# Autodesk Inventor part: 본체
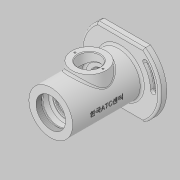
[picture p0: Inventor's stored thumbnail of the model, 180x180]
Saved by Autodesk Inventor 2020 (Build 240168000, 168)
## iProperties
Created: 2022-05
Part Number: 본체
Material: 일반
Document SubType Name: Modeling
Designer: User
Density: 1 g/cm^3
Appearance: 기본값
Mass: 255.264 g
Surface Area: 620.849 cm^2
Volume: 255.264 cm^3
Author: User
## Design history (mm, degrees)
sketch "스케치1"
  geometry: L1 (0, 0)-(115, 0); L2 (115, 0)-(115, 32); L3 (115, 32)-(0, 32); L4 (0, 32)-(0, 0); L5 (0, 22.5)-(8, 22.5); L6 (8, 22.5)-(8, 24); L7 (8, 24)-(11, 24); L8 (11, 24)-(11, 22.5); L9 (11, 22.5)-(22, 22.5); L10 (22, 22.5)-(22, 17.5); L11 (22, 17.5)-(24.25, 17.5); L12 (24.25, 17.5)-(24.25, 18.5); L13 (24.25, 18.5)-(26, 18.5); L14 (26, 18.5)-(26, 17.5); L15 (26, 17.5)-(37, 17.5); L16 (37, 17.5)-(37, 27); L17 (37, 27)-(75, 27); L18 (75, 27)-(75, 17.5); L19 (75, 17.5)-(86, 17.5); L20 (86, 17.5)-(86, 15); L21 (86, 15)-(91, 15); L22 (91, 15)-(91, 11); L23 (91, 11)-(93.7, 11); L24 (93.7, 11)-(93.7, 15); L25 (93.7, 15)-(101, 15); L26 (115, 32)-(115, 36); L27 (115, 36)-(112, 36); L28 (112, 36)-(112, 32); L29 (101, 15)-(101, 20); L30 (101, 20)-(115, 30); L31 (8, 24)-(8, 32); L32 (8, 22.5)-(8, 0)
  constraints: 64 end point, 24 perpendicular, 8 point on line, 3 vertical, 2 horizontal
  dimensions: "d0" = 3 distance of L26.end L27.end; "d1" = 112 distance between parallel lines of L28 L4; "d2" = 64 diameter of L3 L1; "d3" = 45 diameter of L9 L1; "d4" = 54 diameter of L17 L1; "d5" = 22 diameter of L23 L1; "d6" = 30 diameter of L25 L1; "d7" = 40 diameter of L29.end L1; "d8" = 60 diameter of L30.end L1; "d9" = 72 diameter of L27 L1; "d10" = 35 diameter of L15 L1; "d11" = 35 diameter of L11 L1; "d12" = 48 diameter of L7 L1; "d13" = 37 diameter of L13 L1; "d14" = 14 horizontal distance of L30.end L29.end; "d15" = 7.3 distance of L24.end L25.end; "d16" = 5 distance of L20.end L21.end; "d17" = 29 horizontal distance of L30.end L20.end; "d18" = 11 distance of L18.end L19.end; "d19" = 11 distance of L14.end L15.end; "d20" = 38 distance of L16.end L17.end; "d21" = 1.75 distance of L12.end L13.end; "d22" = 4 horizontal distance of L13.end L10.end; "d23" = 8 distance of L5.start L5.end; "d24" = 3 distance of L6.end L7.end; "d25" = 30 diameter of L21 L1; "d26" = 35 diameter of L19 L1
revolve "회전1" stored, may be unused: angle "d27" = 90 deg
sketch "스케치2"
  geometry: C1 r 32 at (0, 0) reference; 2 further points
  constraints: 1 coincident
hole "구멍1" sketch "스케치2" at (0, 0) diameter "d28" = 43.376; stored, may be unused: countersink angle "d32" = 90 deg, drill point angle "d34" = 0 deg; dims "d29" = 8, "d30" = 4, "d31" = 2, "d33" = 9
node "작업 평면1"
sketch "스케치3"
  geometry: L1 (-47, -33.985)-(-47, 33.985); L2 (47, 33.985)-(47, -33.985); L3 (0, 0)-(0, 48); L4 (0, 0)-(-30.854, 36.77); L5 (0, 0)-(0, -48); L6 (0, 0)-(30.854, -36.77); A1 r 48 centre (0, 0) between (0, 48) and (-30.854, 36.77); A2 r 4 centre (-30.854, 36.77) between (-33.425, 39.834) and (-28.283, 33.706); A3 r 58 centre (0, 0) between (47, 33.985) and (-47, 33.985); A4 r 58 centre (0, 0) between (-47, -33.985) and (47, -33.985); A5 r 4 centre (0, 48) between (0, 52) and (0, 44); A6 r 4 centre (0, -48) between (0, -52) and (0, -44); A7 r 4 centre (30.854, -36.77) between (28.283, -33.706) and (33.425, -39.834); A8 r 52 centre (0, 0) between (0, -52) and (33.425, -39.834); A9 r 52 centre (0, 0) between (0, 52) and (-33.425, 39.834); A10 r 44 centre (0, 0) between (0, 44) and (-28.283, 33.706); A11 r 44 centre (0, 0) between (0, -44) and (28.283, -33.706); A12 r 48 centre (0, 0) between (0, -48) and (30.854, -36.77); A13 r 50.25 centre (0, 0) between (0, -50.25) and (32.3, -38.494); A14 r 45.75 centre (0, 0) between (0, -45.75) and (29.408, -35.047); A15 r 2.25 centre (0, -48) between (0, -45.75) and (0, -50.25); A16 r 2.25 centre (30.854, -36.77) between (32.3, -38.494) and (29.408, -35.047); A17 r 48 centre (0, 0) between (0, 48) and (-30.854, 36.77); A18 r 50.25 centre (0, 0) between (0, 50.25) and (-32.3, 38.494); A19 r 45.75 centre (0, 0) between (0, 45.75) and (-29.408, 35.047); A20 r 2.25 centre (0, 48) between (0, 45.75) and (0, 50.25); A21 r 2.25 centre (-30.854, 36.77) between (-32.3, 38.494) and (-29.408, 35.047); 3 further points
  constraints: 44 point on circle, 21 centre point, 12 end point, 12 tangent, 10 coincident, 3 vertical, 2 midpoint, 1 parallel, 1 vertical alignment
  dimensions: "d37" = 96 diameter of A1; "d38" = 40 deg angle of L3 L4; "d39" = 8 diameter of A2; "d40" = 58 radius of A3; "d41" = 58 radius of A4; "d42" = 94 distance between parallel lines of L2 L1; "d44" = 8 diameter of A5; "d47" = 40 deg angle of L6 L5; "d48" = 8 diameter of A6; "d49" = 8 diameter of A7; "d51" = 47 distance between parallel lines of L3 L1 (= 0.5 x d42); "d62" = 4.5 radial gap between concentric circles of A13 A14; "d65" = 4.5 radial gap between concentric circles of A19 A18
extrude "돌출1" join sketch "스케치3" distance "d52" = 10; taper "d53" = 0 deg
revolve "회전2" stored, may be unused: angle "d54" = 90 deg
extrude "돌출3" cut sketch "스케치3" distance "d58" = 4.4; taper "d59" = 0 deg
extrude "돌출4" cut sketch "스케치3" extent not by distance; stored distance "d60" = 0; taper "d61" = 0 deg
extrude "돌출5" cut sketch "스케치3" extent not by distance; stored distance "d63" = 0; taper "d64" = 0 deg
node "작업 평면2"
sketch "스케치4"
  geometry: C1 r 25 at (56, 0); 1 further point
  constraints: 1 centre point, 1 horizontal alignment
  dimensions: "d67" = 50 diameter of C1; "d68" = 56 distance of C1.centre point (0, 0)
extrude "돌출6" join sketch "스케치4" stored distance "d69" = 10; taper "d70" = 5 deg
sketch "스케치5"
  geometry: C1 r 25 at (0, 0) reference; 2 further points
  constraints: 1 coincident
hole "구멍2" sketch "스케치5" at (0, 0) diameter "d71" = 32; stored, may be unused: countersink angle "d75" = 90 deg, drill point angle "d77" = 0 deg; dims "d72" = 90, "d73" = 4, "d74" = 2, "d76" = 38
fillet "모깎기1" dims "d78" = 3
fillet "모깎기2" dims "d79" = 3
fillet "모깎기3" dims "d80" = 0.6
fillet "모깎기4" dims "d81" = 0.5
chamfer "모따기1" distance "d82" = 0.7; stored, may be unused: second distance "d83" = 2, angle "d84" = 30 deg
fillet "모깎기5" dims "d85" = 3
fillet "모깎기6" dims "d86" = 3
fillet "모깎기7" dims "d87" = 3
chamfer "모따기2" distance "d88" = 1; stored, may be unused: second distance "d89" = 2, angle "d90" = 30 deg
chamfer "모따기3" distance "d91" = 1; stored, may be unused: second distance "d92" = 2, angle "d93" = 30 deg
chamfer "모따기4" distance "d94" = 1; stored, may be unused: second distance "d95" = 2, angle "d96" = 30 deg
node "작업 평면3"
sketch "스케치6"
  geometry: L1 (56, -47)-(56, 47) reference; L2 (46, -44)-(46, 44) reference; 3 further points
  constraints: 1 horizontal alignment, 1 midpoint, 1 other
  dimensions: "d97" = 62 distance from line of point (-6, 0) L1
feature "엠보싱1" sketch "스케치6" dims "d0" = 3, "d1" = 112, "d2" = 64, "d3" = 45, "d4" = 54, "d5" = 22, "d6" = 30, "d7" = 40, "d8" = 60, "d9" = 72, "d10" = 35, "d11" = 35, "d12" = 48, "d13" = 37, "d14" = 14, "d15" = 7.3, "d16" = 5, "d17" = 29, "d18" = 11, "d19" = 11, "d20" = 38, "d21" = 1.75, "d22" = 4, "d23" = 8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
sketch "스케치7"
  geometry: L1 (0, 0)-(0, 20.5); C1 r 16 at (0, 0) reference; 2 further points
  constraints: 2 end point, 1 coincident, 1 vertical
  dimensions: "d100" = 20.5 distance of L1.start L1.end
hole "구멍3" sketch "스케치7" at (0, 20.5) diameter "d101" = 2.62111; stored, may be unused: countersink angle "d105" = 90 deg, drill point angle "d107" = 118 deg; dims "d102" = 6, "d103" = 4, "d104" = 2, "d106" = 8
fillet "모깎기8" dims "d111" = 3
chamfer "모따기5" distance "d112" = 1; stored, may be unused: second distance "d113" = 2, angle "d114" = 45 deg
node "솔리드1"
pattern_circular "원형 패턴1" dims angle "d109" = 360 deg
feature "A9D066F2-1C7D-4E18-AEED-F7BC21143FA4" dims "d71" = 32, "d72" = 90, "d73" = 4, "d74" = 2, "d75" = 90 deg, "d76" = 38, "d77" = 0
other parameters: "d57" = -13, "d66" = 38
